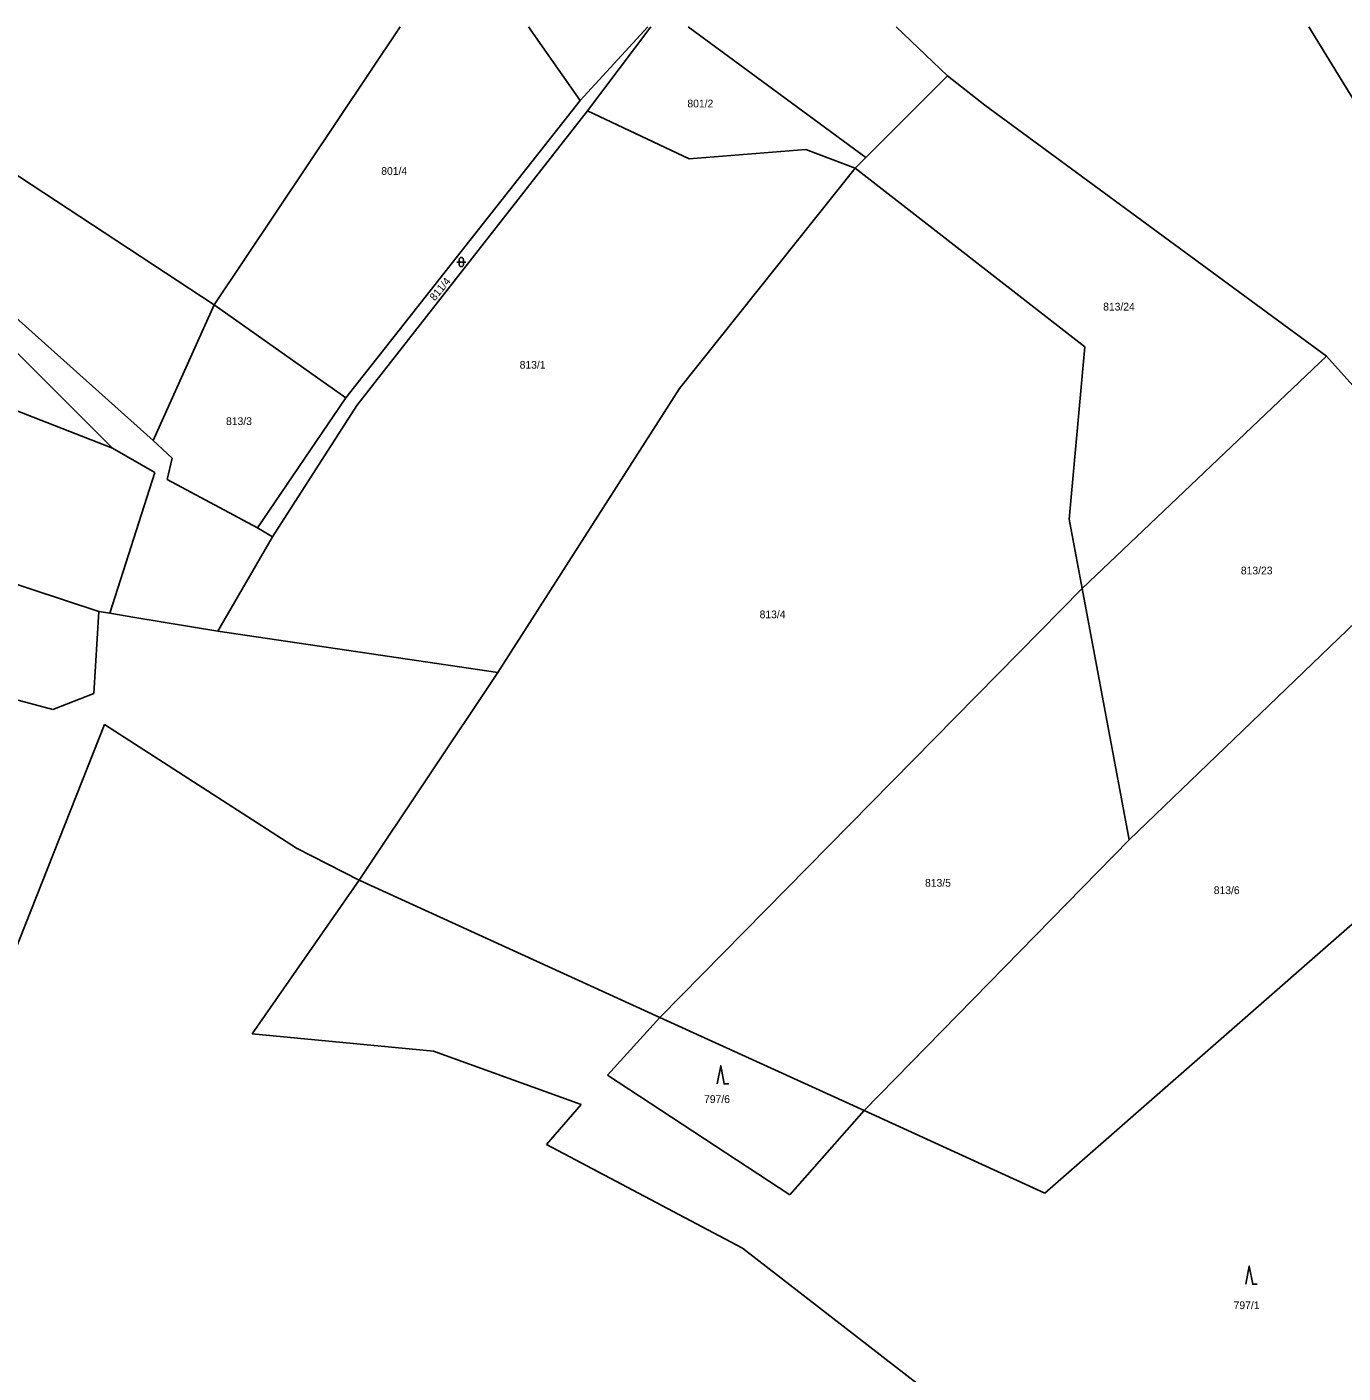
# Model space of a CAD drawing. Extents: x -801907 to -800293, y -1017000 to -1015684.
# Drawn here: x -801306.6 to -801017.4, y -1015981.1 to -1015685.2 of the extents above; entities that cross this region are included whole.
import ezdxf

# ---------------------------------------------------------------- set-up
doc = ezdxf.new("R2010")
doc.units = 0
for name, color, linetype in [('Default', 7, 'Continuous'), ('KN_HRANICE', 7, 'Continuous'), ('KN_KULTURY', 7, 'Continuous'), ('KN_PARCELY', 7, 'Continuous')]:
    doc.layers.add(name, color=color, linetype=linetype)

# ---------------------------------------------------------------- blocks, each defined once
blk = doc.blocks.new('308')
at = {"layer": 'Default'}
blk.add_lwpolyline([(-0.75, 0), (0, 4), (0.75, 0), (1.75, 0)], dxfattribs=at)
blk = doc.blocks.new('316')
at = {"layer": 'Default'}
for points in [[(-1, 1), (0.27, 1), (1, 1)], [(-0.5, 1.5), (-0.4, 1.79), (-0.15, 1.97), (0.16, 1.97), (0.41, 1.79), (0.51, 1.5), (0.51, 0.5), (0.41, 0.21), (0.16, 0.03), (-0.15, 0.03), (-0.4, 0.21), (-0.5, 0.5), (-0.5, 1.5)]]:
    blk.add_lwpolyline(points, dxfattribs=at)

msp = doc.modelspace()

# ---------------------------------------------------------------- linework, layer by layer
at = {"layer": 'KN_HRANICE'}
for p, q in [((-801265.47, -1015746.32), (-801224.62, -1015685.21)), ((-801196.36, -1015685.21), (-801185.03, -1015701.37)), ((-801185.03, -1015701.37), (-801170.14, -1015685.21)), ((-801169.5, -1015685.21), (-801183.43, -1015703.65)), ((-801161.32, -1015685.21), (-801122.25, -1015713.93)), ((-801115.56, -1015685.21), (-801104.3, -1015695.94)), ((-800983.5, -1015752.75), (-801024.84, -1015685.21)), ((-801122.25, -1015713.93), (-801104.3, -1015695.94)), ((-801104.3, -1015695.94), (-801096.07, -1015702.44)), ((-801236.53, -1015766.73), (-801185.03, -1015701.37)), ((-801183.43, -1015703.65), (-801234.15, -1015768.46)), ((-801183.43, -1015703.65), (-801161.06, -1015714.2)), ((-801096.07, -1015702.44), (-801021.02, -1015757.57)), ((-801278.86, -1015776.11), (-801355.45, -1015707.64)), ((-801161.06, -1015714.2), (-801135.45, -1015712.12)), ((-801135.45, -1015712.12), (-801124.58, -1015716.26)), ((-801124.58, -1015716.26), (-801122.25, -1015713.93)), ((-801265.47, -1015746.32), (-801311.03, -1015716.36)), ((-801124.58, -1015716.26), (-801163.18, -1015764.72)), ((-801074.09, -1015755.52), (-801124.58, -1015716.26)), ((-801322.27, -1015743.39), (-801287.84, -1015777.83)), ((-801278.86, -1015776.11), (-801265.47, -1015746.32)), ((-801265.47, -1015746.32), (-801236.53, -1015766.73)), ((-801077.53, -1015793.43), (-801074.09, -1015755.52)), ((-801074.68, -1015808.65), (-801021.02, -1015757.57)), ((-801021.02, -1015757.57), (-800989.74, -1015792.38)), ((-801255.92, -1015795.33), (-801236.53, -1015766.73)), ((-801163.18, -1015764.72), (-801203.11, -1015827.12)), ((-801287.84, -1015777.83), (-801311.64, -1015768.49)), ((-801234.15, -1015768.46), (-801252.66, -1015797.26)), ((-801278.5, -1015783.16), (-801287.84, -1015777.83)), ((-801278.86, -1015776.11), (-801274.67, -1015779.98)), ((-801274.67, -1015779.98), (-801275.84, -1015784.67)), ((-801288.37, -1015814.11), (-801278.5, -1015783.16)), ((-801275.84, -1015784.67), (-801255.92, -1015795.33)), ((-801074.68, -1015808.65), (-801077.53, -1015793.43)), ((-801255.92, -1015795.33), (-801252.66, -1015797.26)), ((-800993.49, -1015795.71), (-801064.33, -1015863.91)), ((-801336.48, -1015798.73), (-801290.84, -1015813.7)), ((-801252.66, -1015797.26), (-801264.69, -1015818.04)), ((-801167.55, -1015902.93), (-801074.68, -1015808.65)), ((-801064.33, -1015863.91), (-801074.68, -1015808.65)), ((-801291.95, -1015831.75), (-801290.84, -1015813.7)), ((-801290.84, -1015813.7), (-801288.37, -1015814.11)), ((-801288.37, -1015814.11), (-801282.91, -1015815.02)), ((-801282.91, -1015815.02), (-801264.69, -1015818.04)), ((-801264.69, -1015818.04), (-801203.11, -1015827.12)), ((-801339.25, -1015825.17), (-801300.97, -1015835.22)), ((-801203.11, -1015827.12), (-801233.6, -1015872.78)), ((-801300.97, -1015835.22), (-801291.95, -1015831.75)), ((-801289.59, -1015838.57), (-801345.03, -1015978.6)), ((-801289.59, -1015838.57), (-801247.4, -1015865.74)), ((-800971.23, -1015843.82), (-801082.92, -1015941.56)), ((-801064.33, -1015863.91), (-801122.63, -1015923.43)), ((-801247.4, -1015865.74), (-801233.6, -1015872.78)), ((-801233.6, -1015872.78), (-801257.11, -1015906.56)), ((-801233.6, -1015872.78), (-801167.55, -1015902.93)), ((-801167.55, -1015902.93), (-801179.02, -1015915.64)), ((-801122.63, -1015923.43), (-801167.55, -1015902.93)), ((-801257.11, -1015906.56), (-801217.23, -1015910.38)), ((-801217.23, -1015910.38), (-801184.83, -1015922.08)), ((-801179.02, -1015915.64), (-801138.96, -1015941.9)), ((-801184.83, -1015922.08), (-801192.44, -1015930.85)), ((-801138.96, -1015941.9), (-801122.63, -1015923.43)), ((-801122.63, -1015923.43), (-801082.92, -1015941.56)), ((-801192.44, -1015930.85), (-801149.32, -1015953.63)), ((-801149.32, -1015953.63), (-801110.32, -1015983.95))]:
    msp.add_line(p, q, dxfattribs=at)

# ---------------------------------------------------------------- block references
at = {"layer": 'KN_KULTURY'}
for name, p in [('316', (-801211.15, -1015737.9)), ('308', (-801154.14, -1015917.57)), ('308', (-801037.97, -1015961.59))]:
    msp.add_blockref(name, p, dxfattribs=at)

# ---------------------------------------------------------------- texts
at = {"layer": 'KN_PARCELY'}
for s, p in [('801/2', (-801161.46, -1015702.9)), ('801/4', (-801228.75, -1015717.73)), ('813/24', (-801070.08, -1015747.55)), ('813/1', (-801198.33, -1015760.33)), ('813/3', (-801262.86, -1015772.72)), ('813/23', (-801039.81, -1015805.55)), ('813/4', (-801145.59, -1015815.19)), ('813/5', (-801109.23, -1015874.2)), ('813/6', (-801045.77, -1015875.82)), ('797/6', (-801157.8, -1015921.74)), ('797/1', (-801041.41, -1015967.06))]:
    msp.add_text(s, height=1.7, dxfattribs=at).set_placement(p)
msp.add_text('811/4', height=1.7, rotation=50.478, dxfattribs=at).set_placement((-801216.99, -1015745.56))

doc.saveas('drawing.dxf')
